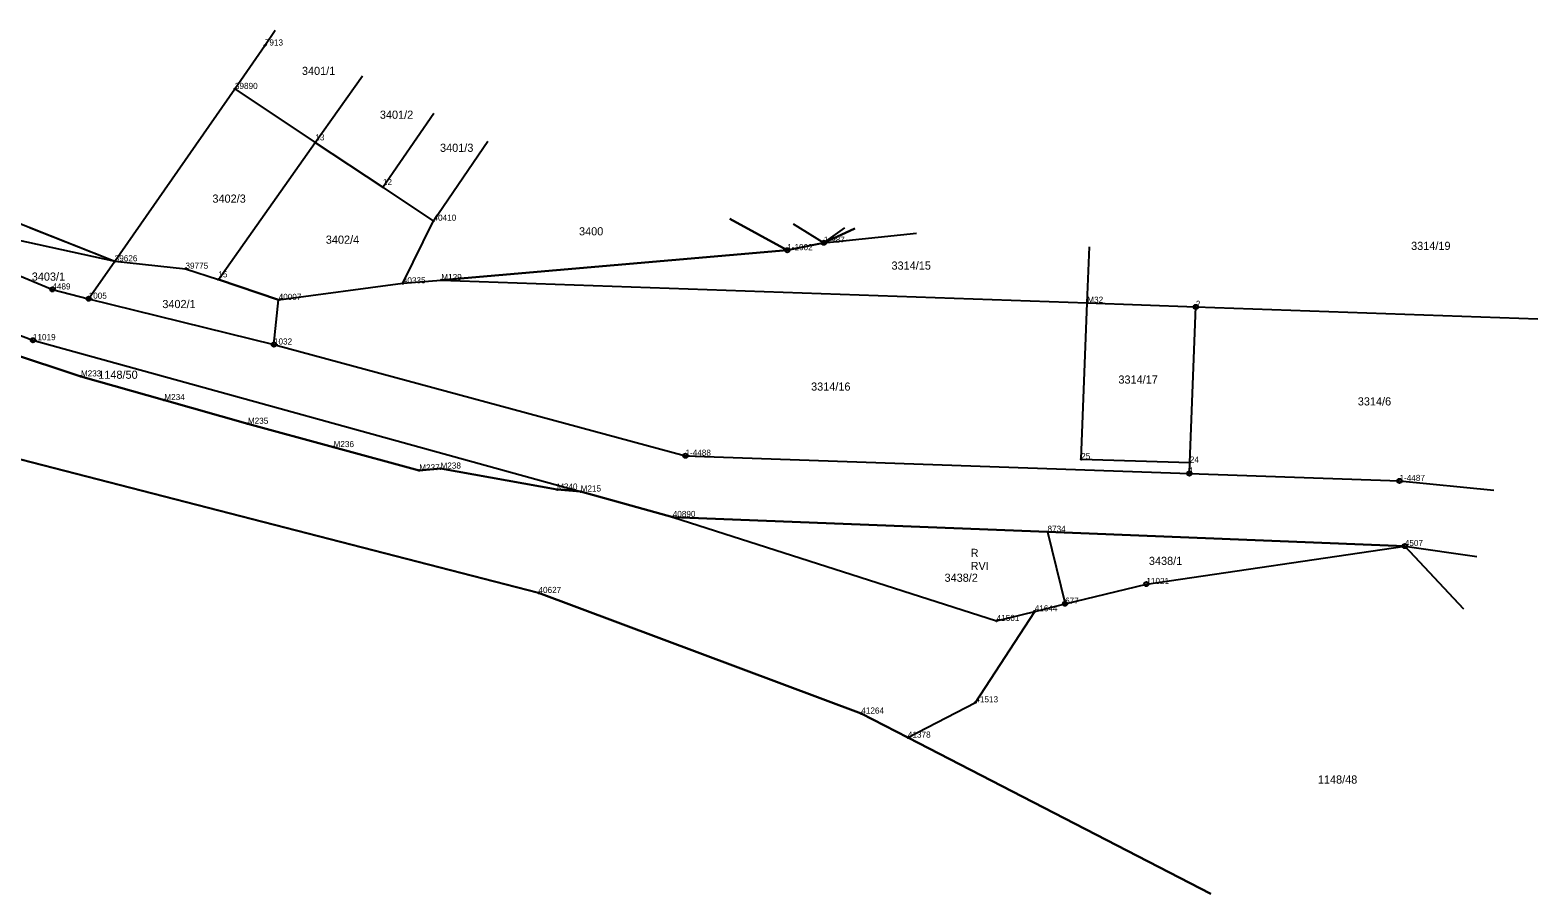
# Model space of a CAD drawing. Extents: x 7492083 to 7492670, y 5466693 to 5467065.
# Drawn here: x 7492392.7 to 7492670.1, y 5466693.1 to 5466852.2 of the extents above; entities that cross this region are included whole.
import ezdxf

# ---------------------------------------------------------------- set-up
doc = ezdxf.new("R2010")
doc.units = 0
for name, color, linetype in [('202-punkt graniczny', 7, 'Continuous'), ('202-punkt graniczny-Atr103', 7, 'Continuous'), ('203-punkt graniczny', 7, 'Continuous'), ('203-punkt graniczny-Atr103', 7, 'Continuous'), ('209-oznaczenie konturu klasyfikacyjnego', 7, 'Continuous'), ('210-oznaczenie konturu użytku gruntowego', 7, 'Continuous'), ('211-numer działki ewidencyjnej', 7, 'Continuous'), ('217-kontur klasyfikacyjny', 7, 'Continuous'), ('218-kontur użytku gruntowego', 7, 'Continuous'), ('219-działka ewidencyjna', 7, 'Continuous')]:
    doc.layers.add(name, color=color, linetype=linetype)

# ---------------------------------------------------------------- blocks, each defined once
blk = doc.blocks.new('202')
blk.add_circle((0, 0), 0.4)
blk = doc.blocks.new('203')
blk.add_circle((0, 0), 0.09)

msp = doc.modelspace()

# ---------------------------------------------------------------- linework, layer by layer
at = {"layer": '217-kontur klasyfikacyjny'}
for points in [[(7492392.56, 5466815.84), (7492408.22, 5466809.61)], [(7492532, 5466811.66), (7492521.44, 5466817.44)], [(7492533.08, 5466816.54), (7492538.74, 5466813.03)], [(7492538.74, 5466813.03), (7492542.61, 5466815.79)], [(7492538.74, 5466813.03), (7492544.42, 5466815.65)], [(7492468.33, 5466806.16), (7492532, 5466811.66)], [(7492408.22, 5466809.61), (7492421.25, 5466808.25)], [(7492421.25, 5466808.25), (7492427.3, 5466806.28)], [(7492427.3, 5466806.28), (7492438.4, 5466802.5)], [(7492438.4, 5466802.5), (7492461.25, 5466805.56)], [(7492461.25, 5466805.56), (7492468.33, 5466806.16)], [(7492510.93, 5466762.53), (7492570.54, 5466743.39)], [(7492579.9, 5466759.79), (7492510.93, 5466762.53)], [(7492645.66, 5466757.18), (7492579.9, 5466759.79)], [(7492598.1, 5466750.19), (7492645.66, 5466757.18)], [(7492583.14, 5466746.57), (7492598.1, 5466750.19)], [(7492577.54, 5466745.16), (7492583.14, 5466746.57)], [(7492570.54, 5466743.39), (7492577.54, 5466745.16)]]:
    msp.add_lwpolyline(points, dxfattribs=at)
at = {"layer": '218-kontur użytku gruntowego'}
for points in [[(7492392.56, 5466815.84), (7492408.22, 5466809.61)], [(7492521.44, 5466817.44), (7492532, 5466811.66)], [(7492533.08, 5466816.54), (7492538.74, 5466813.03)], [(7492538.74, 5466813.03), (7492542.61, 5466815.79)], [(7492544.42, 5466815.65), (7492538.74, 5466813.03)], [(7492538.74, 5466813.03), (7492532, 5466811.66)], [(7492532, 5466811.66), (7492468.33, 5466806.16)], [(7492408.22, 5466809.61), (7492421.25, 5466808.25)], [(7492421.25, 5466808.25), (7492427.3, 5466806.28)], [(7492427.3, 5466806.28), (7492438.4, 5466802.5)], [(7492438.4, 5466802.5), (7492461.25, 5466805.56)], [(7492461.25, 5466805.56), (7492468.33, 5466806.16)], [(7492468.33, 5466806.16), (7492587.22, 5466801.98)], [(7492587.22, 5466801.98), (7492607.2, 5466801.22)], [(7492607.2, 5466801.22), (7492670.14, 5466799.04)], [(7492402, 5466788.41), (7492388.52, 5466792.88)], [(7492417.36, 5466784.06), (7492402, 5466788.41)], [(7492432.73, 5466779.69), (7492417.36, 5466784.06)], [(7492448.5, 5466775.4), (7492432.73, 5466779.69)], [(7492486.22, 5466748.54), (7492386.82, 5466774.16)], [(7492464.27, 5466771.11), (7492448.5, 5466775.4)], [(7492468.18, 5466771.44), (7492464.27, 5466771.11)], [(7492489.64, 5466767.57), (7492468.18, 5466771.44)], [(7492493.97, 5466767.22), (7492489.64, 5466767.57)], [(7492510.93, 5466762.53), (7492493.97, 5466767.22)], [(7492510.93, 5466762.53), (7492570.54, 5466743.39)], [(7492579.9, 5466759.79), (7492510.93, 5466762.53)], [(7492645.66, 5466757.18), (7492579.9, 5466759.79)], [(7492598.1, 5466750.19), (7492645.66, 5466757.18)], [(7492656.47, 5466745.63), (7492645.66, 5466757.18)], [(7492645.66, 5466757.18), (7492658.93, 5466755.24)], [(7492583.14, 5466746.57), (7492598.1, 5466750.19)], [(7492545.63, 5466726.33), (7492486.22, 5466748.54)], [(7492577.54, 5466745.16), (7492583.14, 5466746.57)], [(7492570.54, 5466743.39), (7492577.54, 5466745.16)], [(7492554.21, 5466721.9), (7492545.63, 5466726.33)], [(7492609.99, 5466693.14), (7492554.21, 5466721.9)]]:
    msp.add_lwpolyline(points, dxfattribs=at)
at = {"layer": '219-działka ewidencyjna'}
for points in [[(7492435.86, 5466849.35), (7492437.78, 5466852.18)], [(7492430.35, 5466841.35), (7492435.86, 5466849.35)], [(7492445.15, 5466831.52), (7492453.82, 5466843.78)], [(7492325.52, 5466842.5), (7492408.22, 5466809.61)], [(7492408.22, 5466809.61), (7492430.35, 5466841.35)], [(7492430.35, 5466841.35), (7492445.15, 5466831.52)], [(7492457.59, 5466823.27), (7492466.94, 5466836.91)], [(7492427.3, 5466806.28), (7492445.15, 5466831.52)], [(7492445.15, 5466831.52), (7492457.59, 5466823.27)], [(7492466.9, 5466817.09), (7492476.89, 5466831.71)], [(7492466.9, 5466817.09), (7492457.59, 5466823.27)], [(7492370.62, 5466815.37), (7492396.75, 5466804.43)], [(7492382.09, 5466815.36), (7492408.22, 5466809.61)], [(7492461.25, 5466805.56), (7492466.9, 5466817.09)], [(7492521.44, 5466817.44), (7492532, 5466811.66)], [(7492533.08, 5466816.54), (7492538.74, 5466813.03)], [(7492532, 5466811.66), (7492538.74, 5466813.03)], [(7492538.74, 5466813.03), (7492555.76, 5466814.77)], [(7492349.95, 5466811.49), (7492393.17, 5466795.09)], [(7492468.33, 5466806.16), (7492532, 5466811.66)], [(7492587.22, 5466801.98), (7492587.62, 5466812.29)], [(7492403.43, 5466802.73), (7492408.22, 5466809.61)], [(7492408.22, 5466809.61), (7492421.25, 5466808.25)], [(7492421.25, 5466808.25), (7492427.3, 5466806.28)], [(7492396.75, 5466804.43), (7492403.43, 5466802.73)], [(7492438.4, 5466802.5), (7492427.3, 5466806.28)], [(7492438.4, 5466802.5), (7492461.25, 5466805.56)], [(7492461.25, 5466805.56), (7492468.33, 5466806.16)], [(7492468.33, 5466806.16), (7492587.22, 5466801.98)], [(7492403.43, 5466802.73), (7492437.53, 5466794.29)], [(7492437.53, 5466794.29), (7492438.4, 5466802.5)], [(7492586.1, 5466773.17), (7492587.22, 5466801.98)], [(7492587.22, 5466801.98), (7492607.2, 5466801.22)], [(7492606.09, 5466772.54), (7492607.2, 5466801.22)], [(7492607.2, 5466801.22), (7492670.14, 5466799.04)], [(7492393.17, 5466795.09), (7492493.97, 5466767.22)], [(7492437.53, 5466794.29), (7492513.27, 5466773.81)], [(7492388.52, 5466792.88), (7492402, 5466788.41)], [(7492402, 5466788.41), (7492417.36, 5466784.06)], [(7492417.36, 5466784.06), (7492432.73, 5466779.69)], [(7492432.73, 5466779.69), (7492448.5, 5466775.4)], [(7492386.82, 5466774.16), (7492486.22, 5466748.54)], [(7492448.5, 5466775.4), (7492464.27, 5466771.11)], [(7492513.27, 5466773.81), (7492606.01, 5466770.54)], [(7492464.27, 5466771.11), (7492468.18, 5466771.44)], [(7492468.18, 5466771.44), (7492489.64, 5466767.57)], [(7492586.1, 5466773.17), (7492606.09, 5466772.54)], [(7492606.01, 5466770.54), (7492606.09, 5466772.54)], [(7492606.01, 5466770.54), (7492644.68, 5466769.17)], [(7492644.68, 5466769.17), (7492662.07, 5466767.49)], [(7492489.64, 5466767.57), (7492493.97, 5466767.22)], [(7492493.97, 5466767.22), (7492510.93, 5466762.53)], [(7492510.93, 5466762.53), (7492570.54, 5466743.39)], [(7492510.93, 5466762.53), (7492579.9, 5466759.79)], [(7492579.9, 5466759.79), (7492645.66, 5466757.18)], [(7492579.9, 5466759.79), (7492583.14, 5466746.57)], [(7492598.1, 5466750.19), (7492645.66, 5466757.18)], [(7492645.66, 5466757.18), (7492656.47, 5466745.63)], [(7492645.66, 5466757.18), (7492658.93, 5466755.24)], [(7492583.14, 5466746.57), (7492598.1, 5466750.19)], [(7492486.22, 5466748.54), (7492545.63, 5466726.33)], [(7492577.54, 5466745.16), (7492583.14, 5466746.57)], [(7492566.62, 5466728.4), (7492577.54, 5466745.16)], [(7492570.54, 5466743.39), (7492577.54, 5466745.16)], [(7492554.21, 5466721.9), (7492566.62, 5466728.4)], [(7492545.63, 5466726.33), (7492554.21, 5466721.9)], [(7492554.21, 5466721.9), (7492609.99, 5466693.14)]]:
    msp.add_lwpolyline(points, dxfattribs=at)

# ---------------------------------------------------------------- block references
at = {"layer": '202-punkt graniczny'}
for p in [(7492538.74, 5466813.03), (7492532, 5466811.66), (7492396.75, 5466804.43), (7492403.43, 5466802.73), (7492607.2, 5466801.22), (7492393.17, 5466795.09), (7492437.53, 5466794.29), (7492513.27, 5466773.81), (7492606.01, 5466770.54), (7492644.68, 5466769.17), (7492645.66, 5466757.18), (7492598.1, 5466750.19), (7492583.14, 5466746.57)]:
    msp.add_blockref('202', p, dxfattribs=at)
at = {"layer": '203-punkt graniczny'}
for p in [(7492435.86, 5466849.35), (7492430.35, 5466841.35), (7492445.15, 5466831.52), (7492457.59, 5466823.27), (7492466.9, 5466817.09), (7492408.22, 5466809.61), (7492421.25, 5466808.25), (7492427.3, 5466806.28), (7492461.25, 5466805.56), (7492468.33, 5466806.16), (7492438.4, 5466802.5), (7492587.22, 5466801.98), (7492402, 5466788.41), (7492417.36, 5466784.06), (7492432.73, 5466779.69), (7492448.5, 5466775.4), (7492464.27, 5466771.11), (7492468.18, 5466771.44), (7492586.1, 5466773.17), (7492606.09, 5466772.54), (7492489.64, 5466767.57), (7492493.97, 5466767.22), (7492510.93, 5466762.53), (7492579.9, 5466759.79), (7492486.22, 5466748.54), (7492570.54, 5466743.39), (7492577.54, 5466745.16), (7492566.62, 5466728.4), (7492545.63, 5466726.33), (7492554.21, 5466721.9)]:
    msp.add_blockref('203', p, dxfattribs=at)

# ---------------------------------------------------------------- texts
at = {"layer": '202-punkt graniczny-Atr103'}
for s, height, p in [('1-1002', 1.125, (7492532, 5466811.66)), ('1-987', 1.125, (7492538.74, 5466813.03)), ('4489', 1.125, (7492396.75, 5466804.43)), ('1005', 1.125, (7492403.43, 5466802.73)), ('2', 1.12, (7492607.2, 5466801.22)), ('11019', 1.125, (7492393.17, 5466795.09)), ('1032', 1.125, (7492437.53, 5466794.29)), ('1-4488', 1.125, (7492513.27, 5466773.81)), ('1', 1.12, (7492606.01, 5466770.54)), ('1-4487', 1.125, (7492644.68, 5466769.17)), ('4507', 1.125, (7492645.66, 5466757.18)), ('11021', 1.125, (7492598.1, 5466750.19)), ('677', 1.125, (7492583.14, 5466746.57))]:
    msp.add_text(s, height=height, dxfattribs=at).set_placement(p)
at = {"layer": '203-punkt graniczny-Atr103'}
for s, p in [('7913', (7492435.86, 5466849.35)), ('39890', (7492430.35, 5466841.35)), ('13', (7492445.15, 5466831.89)), ('12', (7492457.59, 5466823.64)), ('40410', (7492466.9, 5466817.09)), ('39626', (7492408.22, 5466809.61)), ('39775', (7492421.25, 5466808.25)), ('15', (7492427.3, 5466806.66)), ('M129', (7492468.33, 5466806.16)), ('40335', (7492461.25, 5466805.56)), ('40007', (7492438.4, 5466802.5)), ('M32', (7492587.22, 5466801.98)), ('M233', (7492402, 5466788.41)), ('M234', (7492417.36, 5466784.06)), ('M235', (7492432.73, 5466779.69)), ('M236', (7492448.5, 5466775.4)), ('25', (7492586.1, 5466773.17)), ('24', (7492606.09, 5466772.54)), ('M237', (7492464.27, 5466771.11)), ('M238', (7492468.18, 5466771.44)), ('M240', (7492489.64, 5466767.57)), ('M215', (7492493.97, 5466767.22)), ('40890', (7492510.93, 5466762.53)), ('8734', (7492579.9, 5466759.79)), ('40627', (7492486.22, 5466748.54)), ('41644', (7492577.54, 5466745.16)), ('41561', (7492570.54, 5466743.39)), ('41513', (7492566.62, 5466728.4)), ('41264', (7492545.63, 5466726.33)), ('41378', (7492554.21, 5466721.9))]:
    msp.add_text(s, height=1.125, dxfattribs=at).set_placement(p)
at = {"layer": '209-oznaczenie konturu klasyfikacyjnego'}
msp.add_text('RVI', height=1.5, dxfattribs=at).set_placement((7492565.75, 5466752.77))
at = {"layer": '210-oznaczenie konturu użytku gruntowego'}
msp.add_text('R', height=1.5, dxfattribs=at).set_placement((7492565.75, 5466755.17))
at = {"layer": '211-numer działki ewidencyjnej'}
for s, p in [('3401/1', (7492442.68, 5466843.93)), ('3401/2', (7492457.03, 5466835.86)), ('3401/3', (7492468.1, 5466829.77)), ('3402/3', (7492426.21, 5466820.41)), ('3400', (7492493.68, 5466814.39)), ('3402/4', (7492447.08, 5466812.85)), ('3314/19', (7492646.82, 5466811.71)), ('3403/1', (7492392.96, 5466806.05)), ('3314/15', (7492551.19, 5466808.08)), ('3402/1', (7492416.99, 5466801)), ('1148/50', (7492405.2, 5466787.98)), ('3314/17', (7492592.95, 5466787.09)), ('3314/16', (7492536.39, 5466785.8)), ('3314/6', (7492637.01, 5466783.07)), ('3438/1', (7492598.56, 5466753.7)), ('3438/2', (7492560.95, 5466750.6)), ('1148/48', (7492629.66, 5466713.44))]:
    msp.add_text(s, height=1.5, dxfattribs=at).set_placement(p)

doc.saveas('drawing.dxf')
